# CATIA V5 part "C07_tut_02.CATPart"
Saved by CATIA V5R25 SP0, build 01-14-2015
Part number: Part1
Bounding box of the stored display mesh (mm): x 0 to 32, y -32 to 32, z -15 to 36
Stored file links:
  E:\ashutosh\Academics\Catia\CATIA V5-6R2013_partfiles\Tutorials_ver_2\C07_tut_02.CATPart
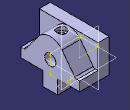
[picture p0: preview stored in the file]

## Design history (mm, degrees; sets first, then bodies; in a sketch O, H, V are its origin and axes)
Body1 (main body)
  Sketch1 on zx-plane, origin (0, 0, 0), H (-1, 0, 0), V (0, 0, 1)
    point P1 (0, 36)
    line L1 (0, 36) -> (0, 0)
    line L2 (0, 0) -> (-32, 0)
    line L3 (0, 36) -> (-12, 36)
    line L4 (-12, 36) -> (-12, 10)
    line L5 (-12, 10) -> (-32, 10)
    line L6 (-32, 10) -> (-32, 0)
    length L1 = 36
    length L2 = 32
    length L3 = 12
    length L6 = 10
    coincidence: P1 V
    vertical: L1 V, L4 V, L6 V
    horizontal: L2 H, L3 H, L5 H
  Pad1: profile Sketch1, direction (0, 1, 0), length 32, mirrored extent
  Sketch2 on face of Pad1 from Sketch1.L6, origin (32, 0, 0), H (0, 1, 0), V (0, 0, 1)
    arc A1 centre (0, 20) radius 16 from (12.8, 29.6) to (-12.8, 29.6) ccw
    point P1 (0, 20)
    reference projected line E1 (-32, 36) -> (32, 36) from edge [face of Pad1 from Sketch1.L4 | face of Pad1 from Sketch1.L3]
    line L1 (-27.5, 10) -> (27.5, 10)
    point P2 (-27.5, 10)
    point P3 (27.5, 10)
    reference projected line E2 (-32, 10) -> (32, 10) from edge [face of Pad1 from Sketch1.L6 | face of Pad1 from Sketch1.L5]
    line L2 (-27.5, 10) -> (-12.8, 29.6)
    line L3 (27.5, 10) -> (12.8, 29.6)
    radius A1 = 16
    length L1 = 55
    coincidence: P1 V, L1 E2
    tangency: A1 E1, L2 A1, L3 A1
    horizontal: L1 H
    symmetry: P3 P2 V
  Pad2: profile Sketch2, direction (1, 0, 0), up to the existing solid (limit type 2)
  Sketch3 on face of Pad2, origin (32, 0, 0), H (0, 1, 0), V (0, 0, 1)
    line L1 (-8, 0) -> (8, 0)
    line L2 (8, 0) -> (8, -15)
    line L3 (8, -15) -> (-8, -15)
    line L4 (-8, -15) -> (-8, 0)
    reference projected line E1 (-32, 0) -> (32, 0) from edge [face of Pad1 from Sketch1.L2 | face of Pad1 from Sketch1.L6]
    length L2 = 15
    length L3 = 16
    horizontal: L1 H, L3 H
    vertical: L2 V, L4 V
    symmetry: L2 L4 V
    coincidence: L1 E1
  Pad3: profile Sketch3, direction (1, 0, 0), up to face of Pad1 from Sketch1.L1
  Sketch4 on zx-plane, origin (0, 0, 0), H (-1, 0, 0), V (0, 0, 1)
    point P1 (-20, 36)
    reference projected line E1 (0, 36) -> (-12, 36) from edge [face of Pad1 from Sketch1.L3 | end face of Pad1]
    reference projected line E2 (0, 0) -> (0, 36) from edge [face of Pad1 from Sketch1.L1 | end face of Pad1]
    distance P1 E2 = 20
    coincidence: P1 E1
  Sketch5 on {plane type Tangent, Support face of Pad2 from Sketch2.A1, RefPoint Sketch4.P1}, origin (20, 0, 36), H (1, 0, 0), V (0, -1, 0)
    point P1 (0, 0)
    reference projected point E1 (0, 0) from Sketch4.P1
    coincidence: E1 P1
  Hole1: placed by Sketch5, at (20, 0, 36) direction (0, 0, -1), diameter 6, depth 16, V-bottom angle 120, counterbore diameter 10, counterbore depth 4
  Sketch6 on face of Pad2, origin (32, 0, 0), H (0, 1, 0), V (0, 0, 1)
    point P1 (0, 14)
    reference projected line E1 (-8, -15) -> (8, -15) from edge [face of Pad3 from Sketch3.L3 | start face of Pad3]
    distance P1 E1 = 29
    coincidence: P1 V
  Sketch7 on face of Pad2, origin (32, 0, 10), H (0, 1, 0), V (0, 0, 1)
    point P1 (0, 4)
    reference projected point E1 (0, 4) from Sketch6.P1
    coincidence: E1 P1
  Hole2: placed by Sketch7, at (32, 0, 14) direction (-1, 0, 0), diameter 12, depth 24
  Fillet1: radius 3, on edge [face of Pad1 from Sketch1.L5 | face of Pad2 from Sketch2.L3]; edge [face of Pad2 from Sketch2.L2 | face of Pad1 from Sketch1.L5]
  Sketch8 on zx-plane, origin (0, 0, 0), H (-1, 0, 0), V (0, 0, 1)
    point P1 (-24, -15)
    point P2 (-8, -15)
    reference projected line E1 (-32, -15) -> (0, -15) from edge [face of Pad3 from Sketch3.L3 | face of Pad3 from Sketch3.L2]
    reference projected line E2 (-32, -15) -> (0, -15) from edge [face of Pad3 from Sketch3.L3 | face of Pad3 from Sketch3.L2]
    reference projected line E3 (-32, -15) -> (-32, 0) from edge [face of Pad3 from Sketch3.L2 | face of Pad2]
    distance E3 P1 = 8
    distance P2 P1 = 16
    coincidence: P1 E1, P2 E2
  Sketch9 on face of Pad3 from Sketch3.L3, origin (8, 0, -15), H (1, 0, 0), V (0, -1, 0)
    point P1 (0, 0)
    reference projected point E1 (0, 0) from Sketch8.P2
    coincidence: E1 P1
  Hole3: placed by Sketch9, at (8, 0, -15) direction (0, 0, 1), diameter 6, depth 16, V-bottom angle 120
  Sketch10 on face of Pad3 from Sketch3.L3, origin (24, 0, -15), H (1, 0, 0), V (0, -1, 0)
    point P1 (0, 0)
    reference projected point E1 (0, 0) from Sketch8.P1
    coincidence: E1 P1
  Hole4: placed by Sketch10, at (24, 0, -15) direction (0, 0, 1), diameter 6, depth 16, V-bottom angle 120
